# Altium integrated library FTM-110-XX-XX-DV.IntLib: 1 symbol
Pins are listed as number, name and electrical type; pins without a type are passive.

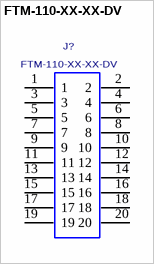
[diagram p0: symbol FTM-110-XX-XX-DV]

## FTM-110-XX-XX-DV
designator J?
1mm x 1mm LOW PROFILE SMT STRIP ASM, 20 Pins.; MANUFACTURER: SAMTEC
footprint FTM-110-XX-XX-DV
pins: 1, 2, 3, 4, 5, 6, 7, 8, 9, 10, 11, 12, 13, 14, 15, 16, 17, 18, 19, 20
